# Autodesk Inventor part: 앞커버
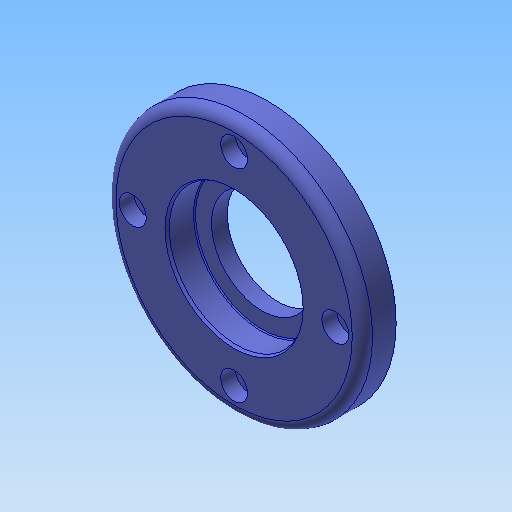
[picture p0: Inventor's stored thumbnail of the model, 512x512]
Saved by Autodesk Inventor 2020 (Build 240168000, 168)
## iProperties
Created: 2010-03
Part Number: 앞커버
Document SubType Name: Modeling
Designer: 진현석
Density: 1 g/cm^3
Material: 알루미늄 6061
Appearance: 기본값(1)
Author: 진현석
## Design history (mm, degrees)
sketch "스케치1"
  geometry: C1 r 38 at (0, 0); 1 further point
  constraints: 1 centre point, 1 coincident
  dimensions: "d56" = 76 diameter of C1
extrude "돌출1" new body sketch "스케치1" distance "d0" = 10; taper "d1" = 0 deg
sketch "스케치2"
  geometry: C1 r 26 at (0, 0); C2 r 38 at (0, 0) reference
  constraints: 1 centre point, 1 concentric
  dimensions: "d51" = 52 diameter of C1
extrude "돌출3" join sketch "스케치2" distance "d4" = 3; taper "d5" = 0 deg
sketch "스케치4"
  geometry: C1 r 38 at (0, 0) reference; C2 r 15 at (0, 0)
  constraints: 1 centre point, 1 coincident
  dimensions: "d22" = 30 diameter of C2
extrude "돌출5" cut sketch "스케치4" extent not by distance; stored distance "d23" = 10; taper "d24" = 0 deg
sketch "스케치6"
  geometry: C1 r 38 at (0, 0) reference; 1 further point
  constraints: 1 vertical alignment
  dimensions: "d32" = 30 distance of C1.centre point (0, 30)
hole "구멍2" sketch "스케치6" at (0, 30) diameter "d33" = 4.5; stored, may be unused: countersink angle "d37" = 90 deg, drill point angle "d39" = 118 deg; dims "d34" = 6, "d35" = 8, "d36" = 4.4, "d38" = 8
sketch "스케치7"
  geometry: C1 r 38 at (0, 0) reference; C2 r 20 at (0, 0)
  constraints: 1 centre point, 1 coincident
  dimensions: "d43" = 40 diameter of C2
extrude "돌출7" cut sketch "스케치7" distance "d44" = 8.3; taper "d45" = 0 deg
chamfer "모따기2" distance "d46" = 0.8; stored, may be unused: second distance "d47" = 2, angle "d48" = 30 deg
fillet "모깎기2" dims "d49" = 0.3
fillet "모깎기3" dims "d50" = 3
chamfer "모따기3" distance "d53" = 1; stored, may be unused: second distance "d54" = 2, angle "d55" = 45 deg
node "솔리드1"
pattern_circular "원형 패턴2" dims angle "d41" = 360 deg
